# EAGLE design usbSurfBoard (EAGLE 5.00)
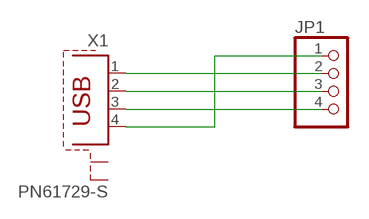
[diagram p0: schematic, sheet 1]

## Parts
JP1  PINHD-1X4  [1X04]
X1  PN61729-S  [PN61729-S]

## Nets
N$1: JP1.2 X1.1
N$2: JP1.3 X1.2
N$3: JP1.4 X1.3
N$4: JP1.1 X1.4
Unconnected: X1.S1 X1.S2

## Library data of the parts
JP1 = pinhead:PINHD-1X4: PIN HEADER
X1 = con-berg:PN61729-S: BERG USB connector

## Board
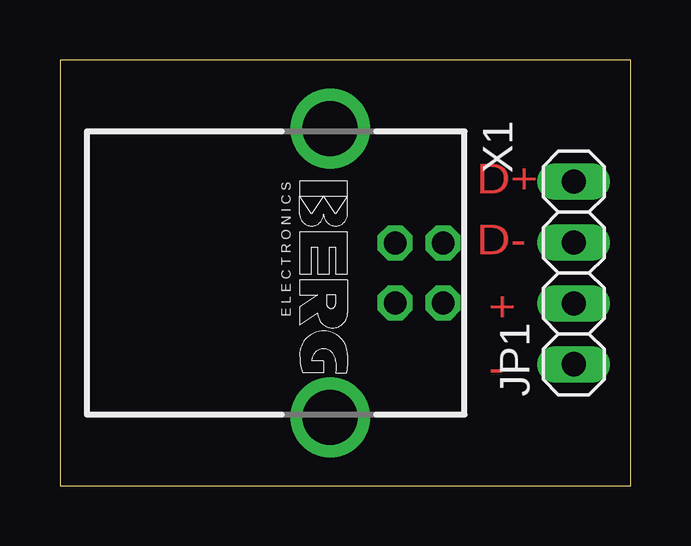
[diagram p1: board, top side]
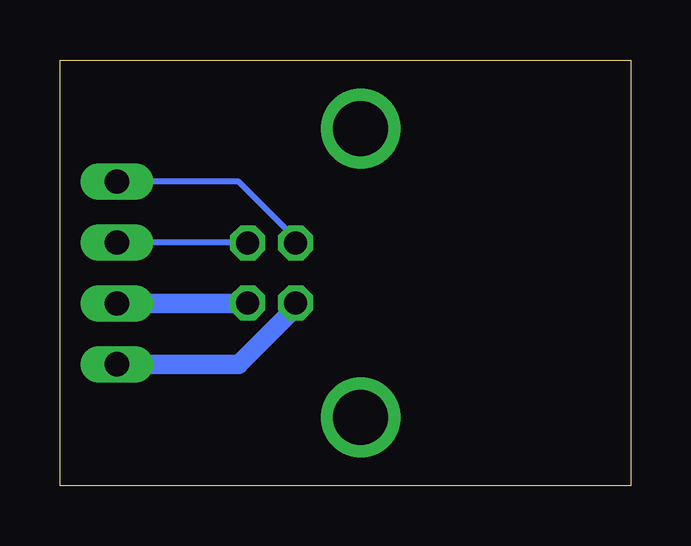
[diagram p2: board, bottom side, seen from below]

Size 23.8 x 17.77 mm. Coordinates in mm from the lower left corner, seen from the top.
Outline: 0,0 23.8,0 23.8,17.77 0,17.77 0,0
Copper layers (1*16): Top 0.035mm / dielectric 1.5mm / Bottom 0.035mm
Design rules "default": minimum track width 10mil, minimum drill 24mil, track to track 8mil, track to pad 8mil, pad to pad 8mil, via to via 8mil, smd to smd 8mil, copper to edge 40mil, drill to drill 8mil, minimum pad ring 10mil, minimum via ring 8mil, stop-mask expansion 4mil, vias tented up to drill 0mil, thermal gap 10mil

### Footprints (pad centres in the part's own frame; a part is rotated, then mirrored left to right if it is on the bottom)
1X04 = drill 1.016 long: 1 -3.81,0; 2 -1.27,0; 3 1.27,0; 4 3.81,0
PN61729-S = drill 0.95 octagon: 1 1.25,4.71; 2 -1.25,4.71; 3 -1.25,2.71; 4 1.25,2.71 | drill 2.3 pad 2.9 round: S1 -6.02,0; S2 6.02,0

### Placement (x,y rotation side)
JP1  21.43,8.88 90 top
X1  11.27,8.88 270 top

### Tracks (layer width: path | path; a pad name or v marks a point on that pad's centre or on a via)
N$1
  Bottom 0.254: X1.1 16.34,7.62
  Bottom 0.813: 16.34,7.62 JP1.2
N$2
  Bottom 0.254: X1.2 16.34,10.16 JP1.3
N$3
  Bottom 0.254: X1.3 13.8,10.16 16.34,12.7 JP1.4
N$4
  Bottom 0.254: X1.4 13.8,7.62
  Bottom 0.813: 13.8,7.62 16.34,5.08 JP1.1

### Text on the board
Top: D+ | D- | + | -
